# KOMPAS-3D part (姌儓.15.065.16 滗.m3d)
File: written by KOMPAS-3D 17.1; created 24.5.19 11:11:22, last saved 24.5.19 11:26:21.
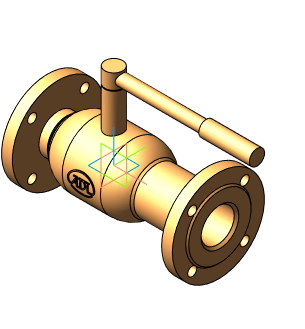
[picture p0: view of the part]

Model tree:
1. Операция без истории:1  (labels: Сталь 20  ГОСТ 1050-2013)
